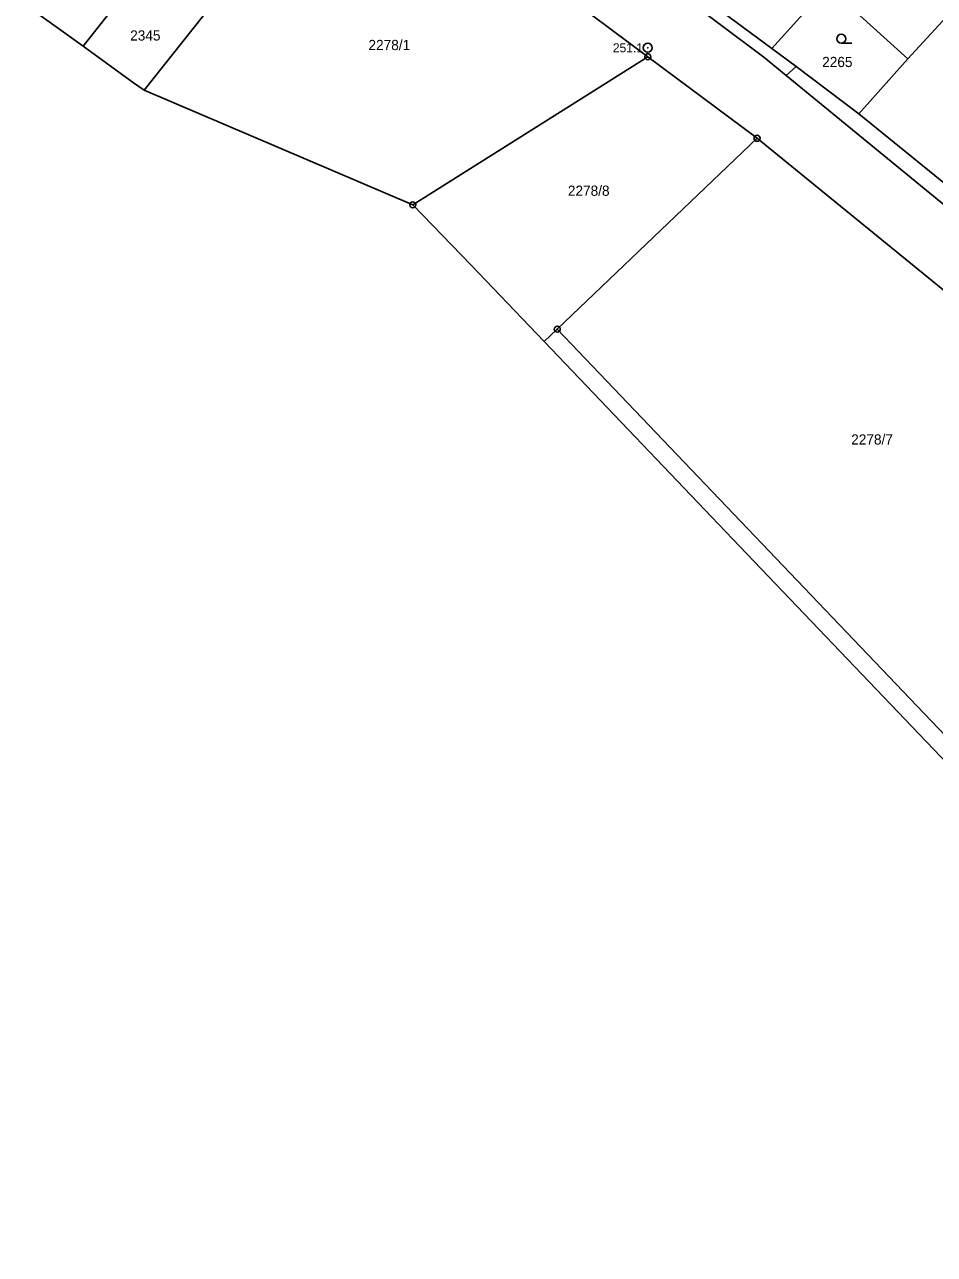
# Model space of a CAD drawing. Extents: x -562167 to -556918, y -1077891 to -1070763.
# Drawn here: x -560980.8 to -560829.1, y -1077794.7 to -1077589.8 of the extents above; entities that cross this region are included whole.
import ezdxf

# ---------------------------------------------------------------- set-up
doc = ezdxf.new("R2010")
doc.units = 0
for name, color, linetype in [('Hranice parcel', 7, 'Continuous'), ('Parcelní čísla', 7, 'Continuous'), ('Značky bodu BP', 7, 'Continuous'), ('Značky kultur', 7, 'Continuous')]:
    doc.layers.add(name, color=color, linetype=linetype)

msp = doc.modelspace()

# ---------------------------------------------------------------- linework, layer by layer
at = {"layer": 'Hranice parcel'}
for p, q in [((-560959.62, -1077578.93), (-560971.06, -1077593.43)), ((-560872.26, -1077581.97), (-560856.26, -1077593.77)), ((-560856.26, -1077593.77), (-560846.91, -1077583.47)), ((-560846.91, -1077583.47), (-560833.59, -1077595.54)), ((-560980.81, -1077586.39), (-560971.06, -1077593.43)), ((-560949.51, -1077586.39), (-560960.9, -1077600.75)), ((-560833.59, -1077595.54), (-560826.48, -1077587.8)), ((-560971.06, -1077593.43), (-560962.64, -1077599.49)), ((-560856.26, -1077593.77), (-560852.2, -1077596.82)), ((-560916.1, -1077619.85), (-560876.92, -1077595.16)), ((-560858.72, -1077608.75), (-560876.92, -1077595.16)), ((-560853.86, -1077598.32), (-560852.2, -1077596.82)), ((-560852.2, -1077596.82), (-560841.77, -1077604.67)), ((-560841.77, -1077604.67), (-560833.59, -1077595.54)), ((-560962.64, -1077599.49), (-560960.9, -1077600.75)), ((-560960.9, -1077600.75), (-560916.1, -1077619.85)), ((-560841.77, -1077604.67), (-560826.12, -1077617.36)), ((-560858.72, -1077608.75), (-560892.02, -1077640.56)), ((-560916.1, -1077619.85), (-560906.37, -1077629.88)), ((-560906.37, -1077629.88), (-560894.18, -1077642.64)), ((-560892.02, -1077640.56), (-560894.18, -1077642.64)), ((-560824.95, -1077710.75), (-560892.02, -1077640.56)), ((-560894.18, -1077642.64), (-560877.81, -1077659.77)), ((-560877.81, -1077659.77), (-560861.63, -1077676.71)), ((-560861.63, -1077676.71), (-560748.88, -1077794.74))]:
    msp.add_line(p, q, dxfattribs=at)
for points in [[(-560876.92, -1077595.16), (-560923.41, -1077560.45), (-560926.17, -1077557.6)], [(-560902.82, -1077561.38), (-560857.61, -1077595.25), (-560853.86, -1077598.32)], [(-560853.86, -1077598.32), (-560800.15, -1077642.27), (-560759.08, -1077677.32), (-560710.12, -1077719.99), (-560671.25, -1077752.44)], [(-560783.44, -1077671.09), (-560799.25, -1077657.15), (-560858.31, -1077609.05), (-560858.72, -1077608.75)]]:
    msp.add_lwpolyline(points, dxfattribs=at)
at = {"layer": 'Značky bodu BP'}
for centre, radius in [((-560876.93, -1077593.68), 0.75), ((-560876.92, -1077595.16), 0.5), ((-560876.93, -1077593.68), 0.03), ((-560876.92, -1077595.16), 0.0303), ((-560858.72, -1077608.75), 0.5), ((-560858.72, -1077608.75), 0.0303), ((-560916.1, -1077619.85), 0.5), ((-560916.1, -1077619.85), 0.0303), ((-560892.02, -1077640.56), 0.5), ((-560892.02, -1077640.56), 0.0303)]:
    msp.add_circle(centre, radius, dxfattribs=at)
at = {"layer": 'Značky kultur'}
msp.add_line((-560844.68, -1077592.93), (-560842.93, -1077592.93), dxfattribs=at)
msp.add_circle((-560844.68, -1077592.18), 0.75, dxfattribs=at)

# ---------------------------------------------------------------- texts
at = {"layer": 'Parcelní čísla'}
for s, p in [('2345', (-560963.21, -1077592.47)), ('2278/1', (-560923.49, -1077594.06)), ('2265', (-560847.86, -1077596.89)), ('2278/8', (-560890.25, -1077618.34)), ('2278/7', (-560843.02, -1077659.79))]:
    msp.add_text(s, height=1.7, dxfattribs=at).set_placement(p)
at = {"layer": 'Značky bodu BP'}
msp.add_text('251.1', height=1.5, dxfattribs=at).set_placement((-560882.75, -1077594.43))

doc.saveas('drawing.dxf')
